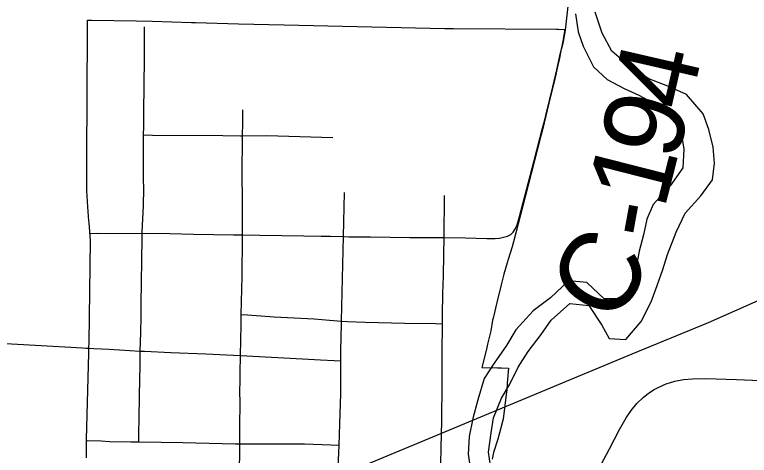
# Model space of a CAD drawing. Extents: x 0 to 45.9, y 0 to 22.
# Drawn here: x 4.674 to 5.194, y 19.171 to 19.483 of the extents above; entities that cross this region are included whole.
import ezdxf

# ---------------------------------------------------------------- set-up
doc = ezdxf.new("R2010")
doc.units = 0
for name, color, linetype in [('GM_X_City_Street', 7, 'Continuous'), ('GM_X_Corporation', 7, 'Continuous'), ('GM_X_County_Road', 7, 'Continuous'), ('GM_X_County_Road_Text', 7, 'Continuous'), ('GM_X_Major_River', 7, 'Continuous'), ('GM_X_Rail_Line', 7, 'Continuous'), ('GM_X_Township_Road', 7, 'Continuous')]:
    doc.layers.add(name, color=color, linetype=linetype)

msp = doc.modelspace()

# ---------------------------------------------------------------- linework, layer by layer
at = {"layer": 'GM_X_City_Street'}
for points in [[(4.76154, 19.18028), (4.76156, 19.18275), (4.7616, 19.18702), (4.76167, 19.196), (4.76205, 19.21334), (4.76233, 19.23455), (4.76239, 19.23944), (4.76254, 19.24451), (4.76292, 19.25797), (4.76307, 19.26875), (4.76323, 19.27993), (4.76339, 19.29145), (4.76366, 19.31032), (4.76377, 19.32273), (4.76395, 19.328), (4.76397, 19.32888), (4.76476, 19.34739), (4.76504, 19.35981), (4.76469, 19.36598), (4.76484, 19.38149), (4.76484, 19.3877), (4.7649, 19.3975), (4.76494, 19.4036), (4.765, 19.41215), (4.76504, 19.41862), (4.76522, 19.42791), (4.76535, 19.43862), (4.76543, 19.44553), (4.76553, 19.45375), (4.76558, 19.45865), (4.76555, 19.47417)], [(4.83279, 19.15772), (4.83306, 19.17632), (4.83305, 19.17894), (4.83298, 19.19185), (4.83323, 19.20739), (4.83311, 19.21664), (4.83315, 19.22283), (4.83316, 19.22592), (4.83326, 19.2321), (4.83344, 19.23827), (4.8335, 19.24137), (4.83392, 19.26313), (4.83406, 19.27037), (4.83464, 19.29732), (4.83497, 19.32519), (4.83497, 19.32678), (4.83499, 19.33318), (4.83488, 19.35225), (4.83479, 19.36857), (4.83503, 19.39698), (4.83511, 19.40595), (4.83524, 19.4153)], [(4.7649, 19.3975), (4.7712, 19.39746), (4.821, 19.39711), (4.83345, 19.39697), (4.83503, 19.39698), (4.85212, 19.39718), (4.88323, 19.39629), (4.89878, 19.39566)], [(4.90224, 19.12008), (4.90254, 19.14957), (4.90268, 19.162), (4.90331, 19.17802), (4.90389, 19.19304), (4.90452, 19.21459), (4.90463, 19.23752), (4.90467, 19.24506), (4.90499, 19.26366), (4.90505, 19.26564), (4.90537, 19.27605), (4.90643, 19.32554), (4.90711, 19.35681)], [(4.72705, 19.32783), (4.73253, 19.32789), (4.75738, 19.32782), (4.76395, 19.328), (4.78357, 19.32766), (4.80019, 19.32737), (4.82858, 19.32688), (4.83497, 19.32678), (4.84718, 19.32657), (4.87826, 19.32606), (4.89065, 19.32592), (4.89725, 19.32585), (4.90643, 19.32554)], [(4.90643, 19.32554), (4.91022, 19.3255), (4.92565, 19.32531), (4.95344, 19.32488), (4.97199, 19.32495), (4.9778, 19.32497)], [(4.9778, 19.32497), (4.99277, 19.32471), (5.00797, 19.32417), (5.01396, 19.32429), (5.01692, 19.32457), (5.01984, 19.32507), (5.02262, 19.32586), (5.02499, 19.32717)], [(4.83406, 19.27037), (4.83843, 19.27014), (4.84163, 19.26997), (4.85744, 19.26886), (4.86678, 19.26819), (4.88568, 19.2673), (4.89651, 19.26646), (4.90505, 19.26564)], [(4.90505, 19.26564), (4.90934, 19.26547), (4.9218, 19.26496), (4.94985, 19.26421), (4.97167, 19.26396), (4.97654, 19.26391)], [(4.76254, 19.24451), (4.76543, 19.24435), (4.78408, 19.24356), (4.80897, 19.24261), (4.8335, 19.24137), (4.87741, 19.23914), (4.89022, 19.23838), (4.89975, 19.23781), (4.90463, 19.23752)], [(4.7248, 19.18133), (4.73473, 19.181), (4.74066, 19.18062), (4.75588, 19.18038), (4.76154, 19.18028), (4.77724, 19.17998), (4.79261, 19.17975), (4.82961, 19.17896), (4.83305, 19.17894), (4.87893, 19.1788), (4.89743, 19.17821), (4.90331, 19.17802)]]:
    msp.add_lwpolyline(points, dxfattribs=at)
at = {"layer": 'GM_X_Corporation'}
msp.add_lwpolyline([(4.72445, 19.16893), (4.72445, 19.17082), (4.72443, 19.17707), (4.72455, 19.18181), (4.7261, 19.24309), (4.72616, 19.24691), (4.72621, 19.25067), (4.72718, 19.32274), (4.72627, 19.33526), (4.72616, 19.3367), (4.72543, 19.34664), (4.72459, 19.35802), (4.7246, 19.36113), (4.7246, 19.36114), (4.72466, 19.37251), (4.72471, 19.38387), (4.72476, 19.39524), (4.72477, 19.39997), (4.72482, 19.40718), (4.72487, 19.41911), (4.72492, 19.43104), (4.72498, 19.44298), (4.72503, 19.45491), (4.72508, 19.46685), (4.72514, 19.47878), (4.72826, 19.47874), (4.75952, 19.47833), (4.77088, 19.47801), (4.79888, 19.47723), (4.80163, 19.47716), (4.83203, 19.47631), (4.86447, 19.47541), (4.97812, 19.47301), (4.98437, 19.4729), (5.05737, 19.47232), (5.05881, 19.47231), (5.06312, 19.47228), (5.06306, 19.47192), (5.06293, 19.4711), (5.06192, 19.46502), (5.06, 19.45466), (5.05932, 19.45158), (5.05827, 19.44687), (5.05732, 19.44258), (5.0568, 19.4404), (5.05531, 19.43415), (5.05198, 19.42012), (5.04751, 19.4021), (5.04599, 19.396), (5.03502, 19.35378), (5.02679, 19.32184), (5.0259, 19.31836), (5.0231, 19.30933), (5.02238, 19.30701), (5.01989, 19.29896), (5.01802, 19.29139), (5.01505, 19.27891), (5.01243, 19.26788), (5.01208, 19.26642), (5.01083, 19.25883), (5.00848, 19.24936), (5.00761, 19.24584), (5.00439, 19.23287), (5.01549, 19.23272), (5.01836, 19.23268), (5.02319, 19.23242), (5.02321, 19.23242), (5.02246, 19.2219), (5.02209, 19.21669), (5.02196, 19.21564), (5.01947, 19.19639), (5.01897, 19.19456), (5.01752, 19.18915), (5.01569, 19.18213), (5.01274, 19.17267), (5.01175, 19.16805)], dxfattribs=at)
at = {"layer": 'GM_X_County_Road'}
for points in [[(5.06359, 19.4717), (5.06549, 19.4888), (5.06713, 19.50492), (5.06976, 19.52932), (5.0717, 19.5509), (5.07372, 19.57245), (5.07446, 19.583), (5.07475, 19.58976), (5.07521, 19.59999), (5.07551, 19.60653), (5.07698, 19.63203), (5.07888, 19.66181), (5.08036, 19.68036), (5.08185, 19.69886), (5.08277, 19.71145)], [(5.02499, 19.32717), (5.0266, 19.32875), (5.02817, 19.33119), (5.02934, 19.33394), (5.0312, 19.3397), (5.04133, 19.37855), (5.04746, 19.40245), (5.04901, 19.40834), (5.04982, 19.41121), (5.05473, 19.43161), (5.0575, 19.44353), (5.06017, 19.45557), (5.06196, 19.46244), (5.06243, 19.46488), (5.06296, 19.46762), (5.06359, 19.4717)], [(4.46946, 19.25992), (4.49624, 19.25883), (4.57664, 19.25459), (4.6416, 19.25133), (4.6756, 19.24937), (4.72162, 19.24686), (4.72426, 19.24667), (4.72634, 19.24652)], [(4.72634, 19.24652), (4.72958, 19.24631), (4.74058, 19.24577), (4.76254, 19.24451)]]:
    msp.add_lwpolyline(points, dxfattribs=at)
at = {"layer": 'GM_X_Major_River'}
for points in [[(5.01052, 19.16355), (5.00921, 19.17307), (5.01101, 19.18671), (5.01275, 19.1973), (5.01834, 19.21124), (5.02423, 19.22099), (5.03016, 19.23302), (5.03721, 19.24427), (5.04655, 19.25623), (5.05358, 19.26634), (5.0667, 19.27821), (5.08031, 19.27679), (5.08948, 19.26292), (5.09458, 19.25333), (5.1063, 19.2527), (5.11717, 19.26539), (5.12428, 19.27929), (5.12869, 19.29097), (5.13271, 19.30228), (5.13597, 19.31285), (5.14198, 19.32867), (5.14832, 19.34221), (5.15956, 19.35451), (5.16775, 19.36574), (5.16913, 19.37748), (5.16824, 19.38889), (5.1651, 19.40149), (5.16117, 19.41259), (5.14934, 19.42613), (5.13621, 19.4321), (5.12269, 19.43732), (5.10961, 19.44557), (5.0966, 19.45685), (5.08967, 19.46953), (5.08469, 19.48445)], [(5.07065, 19.48322), (5.07266, 19.47064), (5.07622, 19.46031), (5.08349, 19.44573), (5.09315, 19.43679), (5.10513, 19.43047), (5.11563, 19.42569), (5.12537, 19.42055), (5.13505, 19.41275), (5.14504, 19.40191), (5.14738, 19.38743), (5.14673, 19.37415), (5.13775, 19.36142), (5.12574, 19.34838), (5.12135, 19.33784), (5.11885, 19.32688), (5.11595, 19.31516), (5.11384, 19.30495), (5.11136, 19.29513), (5.10502, 19.28159), (5.09101, 19.2815), (5.07876, 19.29315), (5.06591, 19.29418), (5.05316, 19.28229), (5.04085, 19.27306), (5.02845, 19.25964), (5.02178, 19.24839), (5.01319, 19.23603), (5.00614, 19.22517), (5.00166, 19.21007), (4.99797, 19.19685), (4.99543, 19.18399), (4.99479, 19.17147), (4.99645, 19.16043)]]:
    msp.add_lwpolyline(points, dxfattribs=at)
at = {"layer": 'GM_X_Rail_Line'}
msp.add_lwpolyline([(2.1, 18.01462), (2.16534, 18.0407), (2.52368, 18.18391), (2.7751, 18.28526), (3.11448, 18.42274), (3.32536, 18.50906), (3.73896, 18.67777), (4.02896, 18.79612), (4.52201, 18.99753), (5.11085, 19.24258), (5.16496, 19.26464), (5.20223, 19.28132), (5.23885, 19.29783), (5.27089, 19.31401), (5.32778, 19.34638), (5.35933, 19.36616), (5.38369, 19.38186), (5.41213, 19.40262), (5.45791, 19.43809), (5.4785, 19.45379)], dxfattribs=at)
at = {"layer": 'GM_X_Township_Road'}
for points in [[(4.9778, 19.32497), (4.97782, 19.32826), (4.97785, 19.33516), (4.97789, 19.34454), (4.97794, 19.35474)], [(4.97654, 19.26391), (4.97656, 19.26676), (4.97663, 19.26983), (4.97686, 19.28523), (4.97715, 19.29754), (4.97752, 19.31298), (4.9778, 19.32497)], [(4.97436, 19.11841), (4.97449, 19.12599), (4.9748, 19.1432), (4.97503, 19.15548), (4.9755, 19.17533), (4.97586, 19.18634), (4.97602, 19.19424), (4.97618, 19.20246), (4.97623, 19.21422), (4.97635, 19.23289), (4.97643, 19.24637), (4.97651, 19.2606), (4.97654, 19.26391)], [(5.08895, 19.16428), (5.09481, 19.17521), (5.1019, 19.18909), (5.10659, 19.19726), (5.11015, 19.20245), (5.1142, 19.20731), (5.11873, 19.21172), (5.12119, 19.21372), (5.12377, 19.21557), (5.12644, 19.21726), (5.12923, 19.21878), (5.13503, 19.22133), (5.14106, 19.22322), (5.14727, 19.22443), (5.15355, 19.22498), (5.16296, 19.22514), (5.18477, 19.22443), (5.219, 19.22287)]]:
    msp.add_lwpolyline(points, dxfattribs=at)

# ---------------------------------------------------------------- texts
at = {"layer": 'GM_X_County_Road_Text'}
for s, rotation, p in [('4', 77.0285, (5.15106, 19.4131)), ('9', 75.8189, (5.14218, 19.3779)), ('1', 75.7139, (5.13351, 19.34387)), ('-', 79.6333, (5.12953, 19.32192)), ('C', 59.3488, (5.09809, 19.26131))]:
    msp.add_text(s, height=0.05682, rotation=rotation, dxfattribs=at).set_placement(p)

doc.saveas('drawing.dxf')
